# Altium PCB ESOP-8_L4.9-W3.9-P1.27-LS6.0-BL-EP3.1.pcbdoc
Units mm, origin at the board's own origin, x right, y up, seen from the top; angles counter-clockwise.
Board outline 18.1 x 19.93 mm, 2 copper layers (Top Layer, Bottom Layer), stack 0 mm thick; 1 components, 0 nets, 9 pads, 0 vias.
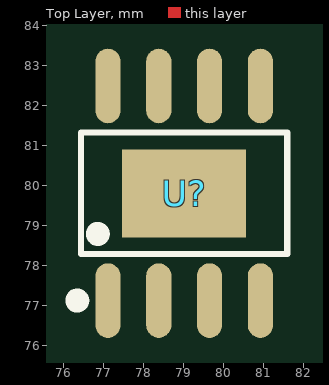
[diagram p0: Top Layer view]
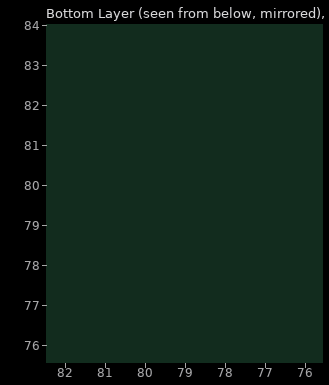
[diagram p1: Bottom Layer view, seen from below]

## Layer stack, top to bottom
Top Layer: signal copper (thickness not stored)
Bottom Layer: signal copper (thickness not stored)

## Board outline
87.949,69.85 69.85,69.85 69.85,89.78 87.949,89.78

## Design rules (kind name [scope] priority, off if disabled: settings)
PasteMaskExpansion "Paste Mask Expansion" [All] p1: expansion=0
SolderMaskExpansion "Solder Mask Expansion" [IsVia] p1: expansion=-25.4 istentingtop=TRUE
SolderMaskExpansion "Solder Mask Expansion" [All] p2: expansion=0.051 istentingtop=FALSE

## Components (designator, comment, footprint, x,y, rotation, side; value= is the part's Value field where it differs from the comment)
U? "" ESOP-8_L4.9-W3.9-P1.27-LS6.0-BL-EP3.1 79.022,79.815 r0 top

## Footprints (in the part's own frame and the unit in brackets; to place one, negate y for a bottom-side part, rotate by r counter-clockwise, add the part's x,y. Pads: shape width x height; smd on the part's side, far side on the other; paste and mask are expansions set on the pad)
ESOP-8_L4.9-W3.9-P1.27-LS6.0-BL-EP3.1 [mm]
  oval 0.63x1.865 smd: 1(-1.905,-2.682) 2(-0.635,-2.682) 3(0.635,-2.682) 4(1.905,-2.682) 5(1.905,2.682) 6(0.635,2.682) 7(-0.635,2.682) 8(-1.905,2.682)
  rect 3.1x2.2 smd paste+0 mask+0.05: 9(0,0)
  silkscreen extent -2.82,-2.83 2.58,1.52

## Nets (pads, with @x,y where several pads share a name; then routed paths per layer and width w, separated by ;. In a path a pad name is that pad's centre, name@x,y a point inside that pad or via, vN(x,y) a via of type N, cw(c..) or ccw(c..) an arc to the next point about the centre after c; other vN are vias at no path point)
pads on no net: U?.1 U?.2 U?.3 U?.4 U?.5 U?.6 U?.7 U?.8 U?.9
